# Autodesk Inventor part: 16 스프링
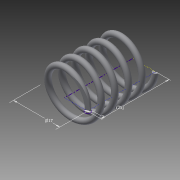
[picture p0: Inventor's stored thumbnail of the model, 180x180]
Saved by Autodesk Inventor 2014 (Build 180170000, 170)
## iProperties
Created: 2016-03
Part Number: 16 스프링
Material: 일반
Document SubType Name: Modeling
Designer: SEC
Density: 1 g/cm^3
Appearance: 기본값
Author: SEC
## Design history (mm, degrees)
sketch "스케치1"
  geometry: L1 (0, 0)-(8.5, 0); L2 (8.5, 0)-(8.5, 17.5); L3 (8.5, 17.5)-(0, 17.5); L4 (0, 17.5)-(0, 0); C1 r 1 at (8.5, 0)
  constraints: 8 end point, 2 parallel, 1 centre point, 1 coincident, 1 horizontal, 1 perpendicular
  dimensions: "d0" = 17 diameter of L2 L4; "d1" = 17.5 distance of L1.end L2.end (derived); "d2" = 2 diameter of C1
feature "코일1" pitch "d3" = 10; turns "d5" = 5; dims "d4" = 17.5 (= d1), "d6" = 0, angle "d7" = 90 deg, angle "d8" = 90 deg, "d9" = 0, "d10" = 0
sketch "스케치2"
  geometry: L1 (-7.5, 0)-(-9.5, 0) reference; 1 further point
  constraints: 1 horizontal alignment
extrude "돌출1" cut sketch "스케치2" stored distance "d11" = 10; taper "d12" = 0 deg
node "작업 평면1"
sketch "스케치3"
  geometry: L1 (-9.5, 0)-(-7.5, 0) reference; 1 further point
  constraints: 1 horizontal alignment
extrude "돌출2" cut sketch "스케치3" stored distance "d13" = 10; taper "d14" = 0 deg
node "솔리드1"
node "절단 모서리 투영1"
node "절단 모서리 투영2"
